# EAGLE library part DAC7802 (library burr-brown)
Dual Monolithic CMOS 12-Bit DAC Multiplying
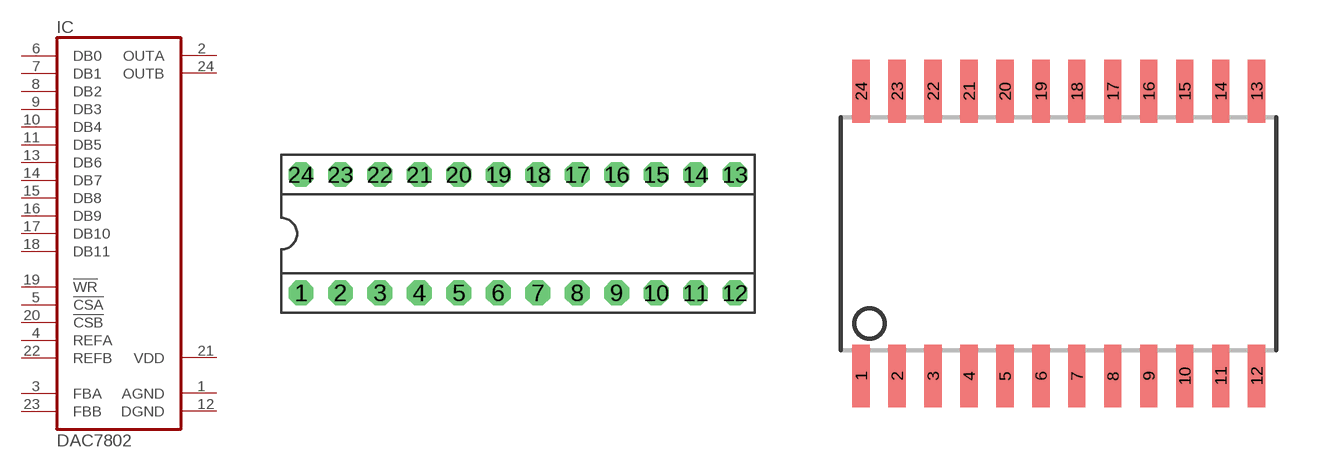
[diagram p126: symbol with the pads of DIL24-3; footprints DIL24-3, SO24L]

Designator prefix IC

## DAC7802P (MPN: DAC7802KP; OC_FARNELL: 1460240; OC_NEWARK: 61M5750)  [DIL24-3]
1  AGND  pwr
2  OUTA  out
3  FBA  pas
4  REFA  in
5  !CSA  in
6  DB0  in
7  DB1  in
8  DB2  in
9  DB3  in
10  DB4  in
11  DB5  in
12  DGND  pwr
13  DB6  in
14  DB7  in
15  DB8  in
16  DB9  in
17  DB10  in
18  DB11  in
19  !WR  in
20  !CSB  in
21  VDD  pwr
22  REFB  in
23  FBB  pas
24  OUTB  out

## DAC7802U (MF: TEXAS INSTRUMENTS; MPN: DAC7802KU; OC_FARNELL: 1295976; OC_NEWARK: 74C9283)  [SO24L]
Pads as for DIL24-3

## Footprint DIL24-3 (pad centres in mm)
Dual In Line 0.3 inch
drill 0.813 pad 1.6 octagon: 1 -13.97,-3.81; 2 -11.43,-3.81; 3 -8.89,-3.81; 4 -6.35,-3.81; 5 -3.81,-3.81; 6 -1.27,-3.81; 7 1.27,-3.81; 8 3.81,-3.81; 9 6.35,-3.81; 10 8.89,-3.81; 11 11.43,-3.81; 12 13.97,-3.81; 13 13.97,3.81; 14 11.43,3.81; 15 8.89,3.81; 16 6.35,3.81; 17 3.81,3.81; 18 1.27,3.81; 19 -1.27,3.81; 20 -3.81,3.81; 21 -6.35,3.81; 22 -8.89,3.81; 23 -11.43,3.81; 24 -13.97,3.81

## Footprint SO24L (pad centres in mm)
Small Outline Package, large
smd 0.61 x 2.21: 1 -6.985,-5.029; 2 -5.715,-5.029; 3 -4.445,-5.029; 4 -3.175,-5.029; 5 -1.905,-5.029; 6 -0.635,-5.029; 7 0.635,-5.029; 8 1.905,-5.029; 9 3.175,-5.029; 10 4.445,-5.029; 11 5.715,-5.029; 12 6.985,-5.029; 13 6.985,5.029; 14 5.715,5.029; 15 4.445,5.029; 16 3.175,5.029; 17 1.905,5.029; 18 0.635,5.029; 19 -0.635,5.029; 20 -1.905,5.029; 21 -3.175,5.029; 22 -4.445,5.029; 23 -5.715,5.029; 24 -6.985,5.029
